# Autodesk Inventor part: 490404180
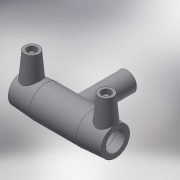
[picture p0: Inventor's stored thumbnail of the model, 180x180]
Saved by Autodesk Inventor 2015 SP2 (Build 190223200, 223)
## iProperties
Created: 2017-06
Part Number: 490404180
Material: Generic
Description: PLASSON TEE 180-180-180
Document SubType Name: Modeling
Designer: KIM
Mass: 57.3761 g
Surface Area: 241.06 cm^2
Volume: 57.3761 cm^3
Density: 1 g/cm^3
Appearance: Default
Author: KIM
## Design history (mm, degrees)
derived "490404.ipt"
feature "Solid1::490404.ipt"
tag "TaggingFeature1"
body "Solid1"
other parameters: "d0" = 422, "d2" = 245, "d3" = 106, "d4" = 105.5, "d5" = 220.5, "d6" = 171, "d8" = 168 deg, "d10" = 42.4, "d11" = 14.13333, "d13" = 422, "d14" = 17.6296, "d17" = 162, "d19" = 3.52592, "d20" = 168 deg, "d22" = 227.85, "d23" = 245, "d24" = 221.0145, "d25" = 135 deg, "d26" = 295.4, "d27" = 135 deg, "d29" = 116, "d30" = 15, "d31" = 168.8, "d34" = 5 deg, "d35" = 15, "d39" = 5 deg, "d40" = 9.6, "d41" = 4.8, "d42" = 6, "d43" = 0, "d45" = 4, "d46" = 14, "d47" = 0, "d51" = 0, "d52" = 144, "d54" = 0, "d55" = 220.5, "d56" = 245, "d57" = 147.7, "d58" = 135 deg, "d59" = 106, "d60" = 106, "d61" = 135 deg, "d72" = 192.01, "d73" = 96.005, "d75" = 189, "d77" = 0, "d78" = 144, "d80" = 0, "d82" = 127.5, "d83" = 0, "d84" = 3, "d85" = 0, "d86" = 3, "d87" = 0, "d88" = 30.74, "d89" = 7.685, "d90" = 30.74, "L_" = 422, "L_1" = 106, "D_" = 245, "A_" = 116, "d_2" = 12
